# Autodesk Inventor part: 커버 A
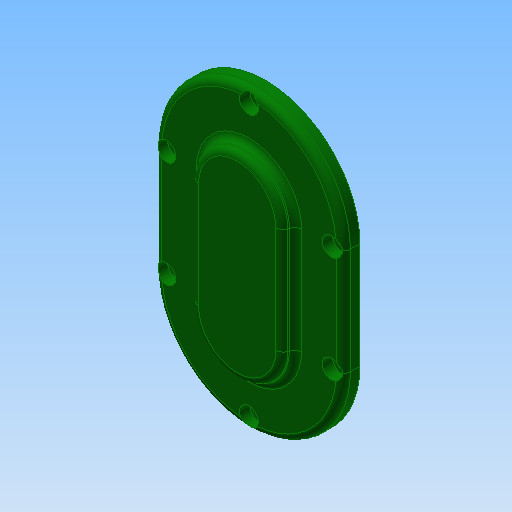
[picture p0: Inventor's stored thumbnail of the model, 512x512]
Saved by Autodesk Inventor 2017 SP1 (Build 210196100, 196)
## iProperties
Created: 2020-04
Part Number: 커버 A
Material: 알루미늄 6061
Document SubType Name: Modeling
Designer: mduedu
Density: 2.71 g/cm^3
Mass: 189.426 g
Surface Area: 209.668 cm^2
Volume: 69.8987 cm^3
Appearance: 진녹색
Author: mduedu
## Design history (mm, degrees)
sketch "스케치1"
  geometry: L1 (-40, 0)-(-40, -45); L2 (40, 0)-(40, -45); A1 r 40 centre (0, 0) between (40, 0) and (-40, 0); A2 r 40 centre (0, -45) between (-40, -45) and (40, -45); 1 further point
  constraints: 4 end point, 4 point on circle, 4 tangent, 2 centre point, 1 coincident, 1 equal radius, 1 vertical alignment
  dimensions: "d0" = 80 diameter of A1; "d31" = 45 distance of point (0, 0) A2.centre
extrude "돌출1" new body sketch "스케치1" distance "d1" = 7; taper "d2" = 0 deg
fillet "모깎기2" dims "d7" = 3
sketch "스케치4"
  geometry: L1 (30, 0)-(30, -45); L2 (-30, 0)-(-30, -45); A1 r 30 centre (0, 0) between (30, 0) and (-30, 0); A2 r 30 centre (0, -45) between (-30, -45) and (30, -45); 1 further point
  constraints: 4 end point, 4 point on circle, 4 tangent, 2 centre point, 1 coincident, 1 equal radius, 1 vertical alignment
  dimensions: "d19" = 60 diameter of A1; "d38" = 45 distance of point (0, 0) A2.centre
extrude "돌출3" join sketch "스케치4" distance "d20" = 4; taper "d21" = 0 deg
sketch "스케치7"
  geometry: L1 (-20, 0)-(-20, -45); L2 (20, 0)-(20, -45); A1 r 20 centre (0, 0) between (20, 0) and (-20, 0); A2 r 20 centre (0, -45) between (-20, -45) and (20, -45); 1 further point
  constraints: 4 end point, 4 point on circle, 4 tangent, 2 centre point, 1 coincident, 1 equal radius, 1 vertical alignment
  dimensions: "d45" = 40 diameter of A1; "d47" = 45 distance of point (0, 0) A2.centre
extrude "돌출5" join sketch "스케치7" distance "d48" = 5; taper "d49" = -15 deg
fillet "모깎기4" dims "d50" = 3
chamfer "모따기2" distance "d58" = 1; stored, may be unused: second distance "d59" = 2, angle "d60" = 45 deg
sketch "스케치6"
  geometry: L1 (0, 7)-(37, 7) reference; L2 (0, -4)-(30, -4) reference; L3 (0, -4)-(0, 8); L4 (0, 8)-(8, 8); L5 (11, 5)-(11, 5); L6 (11, 5)-(16, 5); L7 (16, 5)-(16, -4); L8 (-45, -4)-(-45, 8); L9 (-45, 8)-(-37, 8); L10 (-34, 5)-(-34, 4); L11 (-34, 4)-(-31, 4); L12 (-31, 4)-(-31, -4); L13 (-31, -4)-(-45, -4); A1 r 3 centre (8, 5) between (11, 5) and (8, 8); A2 r 3 centre (-37, 5) between (-34, 5) and (-37, 8); 3 further points
  constraints: 22 end point, 5 parallel, 5 point on line, 4 perpendicular, 4 point on circle, 4 tangent, 2 centre point, 2 horizontal alignment, 1 horizontal, 1 vertical
  dimensions: "d39" = 32 diameter of L7 L3; "d41" = 3 distance of point (11, 8) L5.end; "d42" = 9 distance of L6.end L7.end; "d43" = 22 diameter of L5 L3; "d44" = 3 radius of A1; "d51" = 8 distance of L11.end L12.end; "d52" = 45 distance of L2.start L8.start; "d53" = 28 diameter of L12 L8; "d54" = 22 diameter of L10 L8; "d55" = 3 radius of A2
revolve "회전1" stored, may be unused: angle "d56" = 90 deg
revolve "회전2" stored, may be unused: angle "d57" = 90 deg
sketch "스케치3"
  geometry: A1 r 35 centre (0, 0) between (0, 35) and (-35, 0); A2 r 35 centre (0, -45) between (-35, -45) and (0, -80); 3 further points
  constraints: 6 point on circle, 5 vertical alignment, 2 centre point, 2 horizontal alignment, 1 coincident, 1 equal radius
  dimensions: "d8" = 70 diameter of A1; "d69" = 45 distance of point (0, 0) A2.centre
hole "구멍1" sketch "스케치3" at (0, 35), (-35, 0), (-35, -45), (0, -80), (35, -45), (35, 0) diameter "d9" = 4.5; stored, may be unused: countersink angle "d13" = 90 deg, drill point angle "d15" = 118 deg; dims "d10" = 6, "d11" = 8, "d12" = 4.4, "d14" = 8
fillet "모깎기5" dims "d70" = 0.3
chamfer "모따기3" distance "d71" = 1; stored, may be unused: second distance "d72" = 2, angle "d73" = 45 deg
node "솔리드1"
